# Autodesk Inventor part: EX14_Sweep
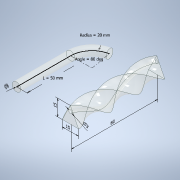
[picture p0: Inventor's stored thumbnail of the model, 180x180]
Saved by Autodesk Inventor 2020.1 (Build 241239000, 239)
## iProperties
Created: 2019-10
Part Number: EX14_Sweep
Material: Nickel-Copper Alloy 400
Document SubType Name: Modeling
Designer: Synergysoft Dell02
Density: 8.83 g/cm^3
Appearance: Clear
Author: Synergysoft Dell02
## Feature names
1. Sweep1
2. Sweep2
## Parameters: Angle = 80 deg, d3 = 8 mm, d4 = 0, d5 = 0, d6 = 15 mm, d7 = 5 mm, d8 = 15 mm, d11 = 0, d12 = 360 deg, d14 = 3 mm, d16 = 5.57743 mm, d17 = 1.93905 mm, d19 = -26.96064 mm, d20 = 3 mm, d21 = 0, d23 = 15 mm, d24 = 4.76607 mm, d25 = 15 mm, d26 = 7.31899 mm, d27 = 8 mm
